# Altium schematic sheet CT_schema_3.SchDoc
size 362 x 192 mm
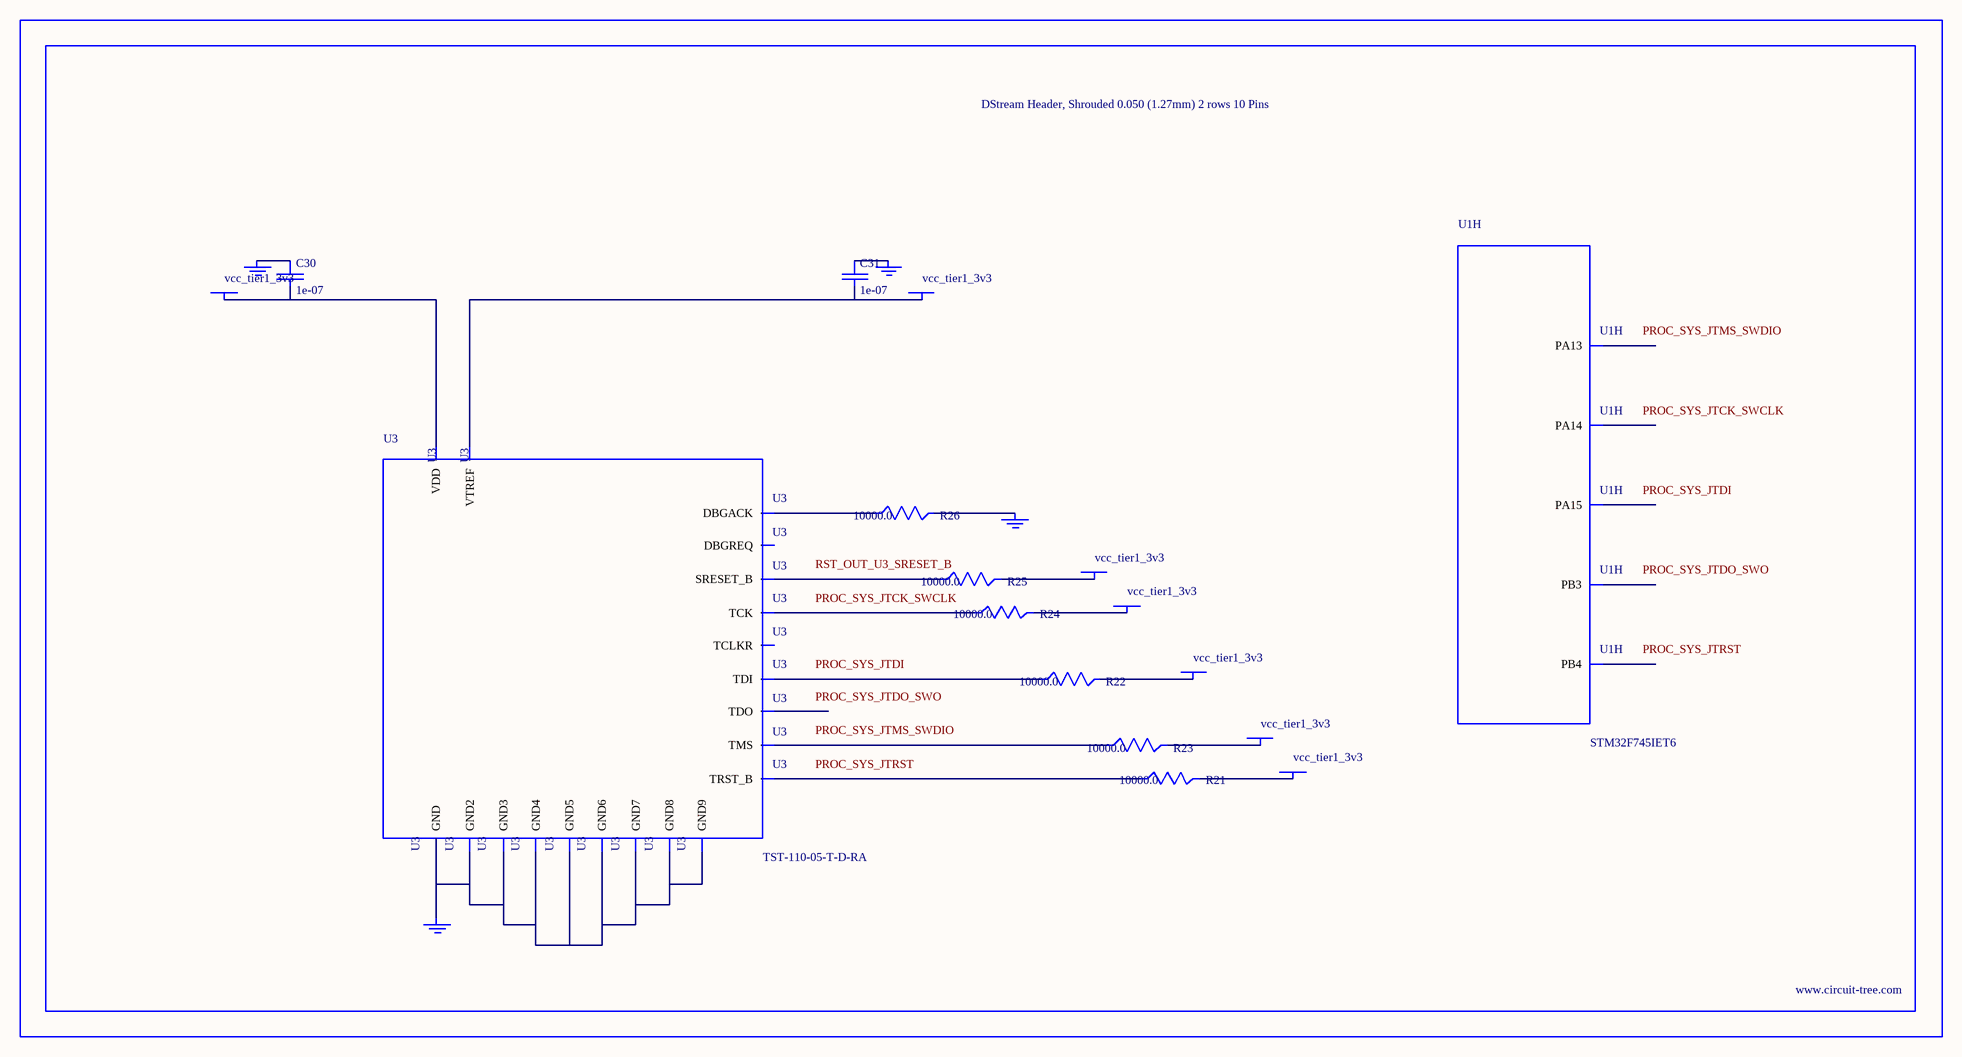
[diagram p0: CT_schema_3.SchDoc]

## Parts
BORDER2  (no value)
C30  1e-07  [C0402]
C31  1e-07  [C0402]
GND_INSTANCE_2_0  (no value)
GND_INSTANCE_2_1  (no value)
GND_INSTANCE_2_2  (no value)
GND_INSTANCE_2_3  (no value)
POWER_INSTANCE_2_0  vcc_tier1_3v3
POWER_INSTANCE_2_1  vcc_tier1_3v3
POWER_INSTANCE_2_2  vcc_tier1_3v3
POWER_INSTANCE_2_3  vcc_tier1_3v3
POWER_INSTANCE_2_4  vcc_tier1_3v3
POWER_INSTANCE_2_5  vcc_tier1_3v3
POWER_INSTANCE_2_6  vcc_tier1_3v3
R21  10000.0  [R0603]
R22  10000.0  [R0603]
R23  10000.0  [R0603]
R24  10000.0  [R0603]
R25  10000.0  [R0603]
R26  10000.0  [R0603]
U1  STM32F745IET6  [LQFP176]  (part H of 14)
U3  TST-110-05-T-D-RA  [TST-110-05-T-D-RA]

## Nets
NetC30_1: C30.1 GND_INSTANCE_2_1.0(GND)
NetC30_2: C30.2 POWER_INSTANCE_2_1.0(PWR) U3.2(VDD)
NetC31_1: C31.1 GND_INSTANCE_2_0.0(GND)
NetC31_2: C31.2 POWER_INSTANCE_2_0.0(PWR) U3.1(VTREF)
NetGND_INSTANCE_2_2_0: GND_INSTANCE_2_2.0(GND) R26.2
NetGND_INSTANCE_2_3_0: GND_INSTANCE_2_3.0(GND) U3.4(GND) U3.6(GND2) U3.8(GND3) U3.10(GND4) U3.12(GND5) U3.14(GND6) U3.16(GND7) U3.18(GND8) U3.20(GND9)
NetPOWER_INSTANCE_2_2_0: POWER_INSTANCE_2_2.0(PWR) R21.2
NetPOWER_INSTANCE_2_3_0: POWER_INSTANCE_2_3.0(PWR) R22.2
NetPOWER_INSTANCE_2_4_0: POWER_INSTANCE_2_4.0(PWR) R23.2
NetPOWER_INSTANCE_2_5_0: POWER_INSTANCE_2_5.0(PWR) R24.2
NetPOWER_INSTANCE_2_6_0: POWER_INSTANCE_2_6.0(PWR) R25.2
NetR21_1: R21.1 U3.3(TRST_B)
NetR22_1: R22.1 U3.5(TDI)
NetR23_1: R23.1 U3.7(TMS)
NetR24_1: R24.1 U3.9(TCK)
NetR25_1: R25.1 U3.15(SRESET_B)
NetR26_1: R26.1 U3.19(DBGACK)

Not connected (* = marked no-connect by the designer): U1 124(PA13) 137(PA14) 138(PA15) 161(PB3) 162(PB4); U3 11(TCLKR) 13(TDO) 17(DBGREQ)

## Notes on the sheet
- Labels drawn without touching a wire or pin: PROC_SYS_JTCK_SWCLK, PROC_SYS_JTDI, PROC_SYS_JTDO_SWO, PROC_SYS_JTMS_SWDIO, PROC_SYS_JTRST, RST_OUT_U3_SRESET_B

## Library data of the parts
BORDER2 = BORDER_PAGE2
C30 C31 = C0402C104K3RACTU
GND_INSTANCE_2_0-GND_INSTANCE_2_3 = GND
POWER_INSTANCE_2_0-POWER_INSTANCE_2_6 = PWR
R21-R26 = RC0603JR-0710KL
